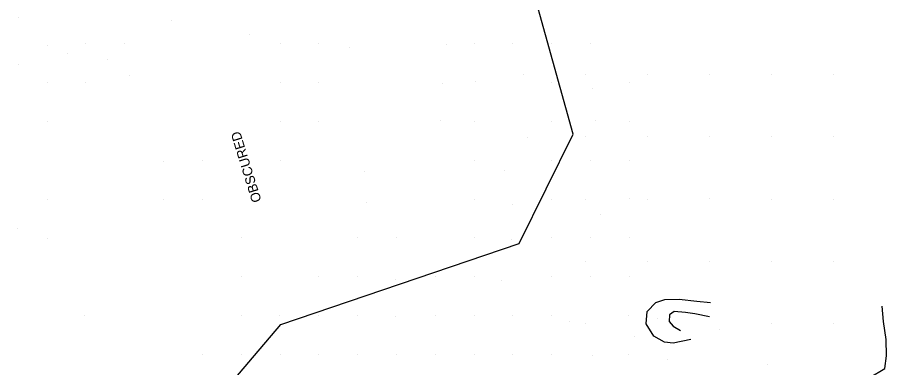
# Model space of a CAD drawing. Extents: x 524772 to 528246, y 273285 to 283088.
# Drawn here: x 527181.2 to 527317.8, y 274859.7 to 274914.7 of the extents above; entities that cross this region are included whole.
import ezdxf

# ---------------------------------------------------------------- set-up
doc = ezdxf.new("R2010")
doc.units = 0
for name, color, linetype in [('PH Exist DTM Breakline', 7, 'Continuous'), ('PH Exist DTM Obscure Area', 7, 'Continuous'), ('PH Exist DTM Obscure Area Text', 7, 'Continuous'), ('PH Exist DTM Point', 7, 'Continuous')]:
    doc.layers.add(name, color=color, linetype=linetype)

msp = doc.modelspace()

# ---------------------------------------------------------------- linework, layer by layer
at = {"layer": 'PH Exist DTM Breakline'}
for points in [[(527287, 274864.1), (527284.25, 274863.56), (527282.89, 274863.68), (527281.18, 274864.65), (527280.02, 274866.57), (527280.18, 274868.54), (527281.52, 274869.95), (527282.93, 274870.39), (527285.19, 274870.48), (527287.96, 274870.15), (527290.11, 274869.94)], [(527271.15, 274837.77), (527278.4, 274842.24), (527286.33, 274846.53), (527291.36, 274848.79), (527295.71, 274850.41), (527301.1, 274852.6), (527304.14, 274853.89), (527307.96, 274855.03), (527311.22, 274856.23), (527313.42, 274857.08), (527315.02, 274858.09), (527317.47, 274859.54), (527317.76, 274861.55), (527317.68, 274864.13), (527317.28, 274866.96), (527317.07, 274869.38)], [(527289.96, 274867.66), (527287.65, 274868.18), (527286.2, 274868.38), (527284.4, 274868.53), (527283.69, 274868), (527283.62, 274866.93), (527284.22, 274866.22), (527285.39, 274865.52)]]:
    msp.add_lwpolyline(points, dxfattribs=at)
at = {"layer": 'PH Exist DTM Obscure Area'}
msp.add_lwpolyline([(527193.38, 274832.02), (527222.62, 274866.47), (527260.08, 274879.19), (527268.55, 274896.41), (527257.79, 274935.01)], dxfattribs=at)
at = {"layer": 'PH Exist DTM Point'}
for p, q in [((527181.36, 274914.74), (527181.36, 274914.74)), ((527205.52, 274914.28), (527205.52, 274914.28)), ((527217.68, 274912.04), (527217.68, 274912.04)), ((527185.95, 274910.34), (527185.95, 274910.34)), ((527192.01, 274910.64), (527192.01, 274910.64)), ((527198.12, 274910.57), (527198.12, 274910.57)), ((527222.5, 274910.57), (527222.5, 274910.57)), ((527228.6, 274910.57), (527228.6, 274910.57)), ((527233.38, 274910.08), (527233.38, 274910.08)), ((527248.63, 274910.49), (527248.63, 274910.49)), ((527252.98, 274910.57), (527252.98, 274910.57)), ((527259.08, 274910.57), (527259.08, 274910.57)), ((527265.17, 274910.59), (527265.17, 274910.59)), ((527271.27, 274910.57), (527271.27, 274910.57)), ((527189.07, 274909.13), (527189.07, 274909.13)), ((527181.47, 274907.26), (527181.47, 274907.26)), ((527195.47, 274908.15), (527195.47, 274908.15)), ((527198.86, 274905.65), (527198.86, 274905.65)), ((527260.72, 274905.7), (527260.72, 274905.7)), ((527270.48, 274905.7), (527270.48, 274905.7)), ((527280.23, 274905.7), (527280.23, 274905.7)), ((527289.98, 274905.7), (527289.98, 274905.7)), ((527299.74, 274905.7), (527299.74, 274905.7)), ((527309.49, 274905.7), (527309.49, 274905.7)), ((527185.92, 274904.49), (527185.92, 274904.49)), ((527192.02, 274904.46), (527192.02, 274904.46)), ((527222.5, 274904.48), (527222.5, 274904.48)), ((527228.6, 274904.48), (527228.6, 274904.48)), ((527247.96, 274904.39), (527247.96, 274904.39)), ((527253.13, 274904.59), (527253.13, 274904.59)), ((527265.17, 274904.48), (527265.17, 274904.48)), ((527277.36, 274904.48), (527277.36, 274904.48)), ((527271.62, 274903.59), (527271.62, 274903.59)), ((527185.92, 274898.38), (527185.92, 274898.38)), ((527222.5, 274898.38), (527222.5, 274898.38)), ((527228.6, 274898.38), (527228.6, 274898.38)), ((527247.69, 274898.59), (527247.69, 274898.59)), ((527252.98, 274898.38), (527252.98, 274898.38)), ((527265.17, 274898.38), (527265.17, 274898.38)), ((527272.05, 274898.53), (527272.05, 274898.53)), ((527277.36, 274898.38), (527277.36, 274898.38)), ((527270.48, 274895.95), (527270.48, 274895.95)), ((527280.23, 274895.95), (527280.23, 274895.95)), ((527289.98, 274895.95), (527289.98, 274895.95)), ((527299.74, 274895.95), (527299.74, 274895.95)), ((527309.49, 274895.95), (527309.49, 274895.95)), ((527261.43, 274895.94), (527261.43, 274895.94)), ((527204.25, 274892.16), (527204.25, 274892.16)), ((527210.31, 274892.28), (527210.31, 274892.28)), ((527222.5, 274892.28), (527222.5, 274892.28)), ((527252.98, 274892.28), (527252.98, 274892.28)), ((527265.18, 274892.3), (527265.18, 274892.3)), ((527271.29, 274892.2), (527271.29, 274892.2)), ((527277.34, 274892.32), (527277.34, 274892.32)), ((527235.8, 274890.57), (527235.8, 274890.57)), ((527257.74, 274890.66), (527257.74, 274890.66)), ((527185.93, 274886.17), (527185.93, 274886.17)), ((527204.21, 274886.19), (527204.21, 274886.19)), ((527210.31, 274886.17), (527210.31, 274886.17)), ((527236.03, 274885.72), (527236.03, 274885.72)), ((527252.98, 274886.19), (527252.98, 274886.19)), ((527258.99, 274885.41), (527258.99, 274885.41)), ((527265.19, 274886.19), (527265.19, 274886.19)), ((527270.48, 274886.19), (527270.48, 274886.19)), ((527277.36, 274886.2), (527277.36, 274886.2)), ((527280.23, 274886.19), (527280.23, 274886.19)), ((527289.96, 274886.21), (527289.96, 274886.21)), ((527299.74, 274886.19), (527299.74, 274886.19)), ((527309.49, 274886.19), (527309.49, 274886.19)), ((527272.78, 274883.71), (527272.78, 274883.71)), ((527181.25, 274881.61), (527181.25, 274881.61)), ((527185.93, 274880.06), (527185.93, 274880.06)), ((527216.4, 274880.09), (527216.4, 274880.09)), ((527234.69, 274880.09), (527234.69, 274880.09)), ((527240.79, 274880.08), (527240.79, 274880.08)), ((527252.98, 274880.09), (527252.98, 274880.09)), ((527258.8, 274879.83), (527258.8, 274879.83)), ((527265.16, 274880.09), (527265.16, 274880.09)), ((527271.27, 274880.09), (527271.27, 274880.09)), ((527277.36, 274880.09), (527277.36, 274880.09)), ((527270.48, 274876.44), (527270.48, 274876.44)), ((527280.23, 274876.44), (527280.23, 274876.44)), ((527290.01, 274876.43), (527290.01, 274876.43)), ((527299.74, 274876.44), (527299.74, 274876.44)), ((527309.49, 274876.44), (527309.49, 274876.44)), ((527216.4, 274874), (527216.4, 274874)), ((527228.6, 274874), (527228.6, 274874)), ((527234.69, 274874), (527234.69, 274874)), ((527240.69, 274873.51), (527240.69, 274873.51)), ((527246.88, 274874), (527246.88, 274874)), ((527253.03, 274873.96), (527253.03, 274873.96)), ((527257.21, 274873.42), (527257.21, 274873.42)), ((527265.17, 274874), (527265.17, 274874)), ((527271.27, 274873.98), (527271.27, 274873.98)), ((527277.36, 274874), (527277.36, 274874)), ((527191.77, 274867.83), (527191.77, 274867.83)), ((527216.4, 274867.91), (527216.4, 274867.91)), ((527222.49, 274867.88), (527222.49, 274867.88)), ((527228.6, 274867.9), (527228.6, 274867.9)), ((527234.71, 274867.9), (527234.71, 274867.9)), ((527240.59, 274867.68), (527240.59, 274867.68)), ((527246.88, 274867.9), (527246.88, 274867.9)), ((527252.98, 274867.9), (527252.98, 274867.9)), ((527259.08, 274867.88), (527259.08, 274867.88)), ((527265.17, 274867.9), (527265.17, 274867.9)), ((527277.27, 274867.87), (527277.27, 274867.87)), ((527281.71, 274867.36), (527281.71, 274867.36)), ((527267.94, 274866.96), (527267.94, 274866.96)), ((527270.48, 274866.69), (527270.48, 274866.69)), ((527299.74, 274866.69), (527299.74, 274866.69)), ((527309.49, 274866.69), (527309.49, 274866.69)), ((527278.2, 274864.64), (527278.2, 274864.64)), ((527291.47, 274865.67), (527291.47, 274865.67)), ((527216.4, 274861.82), (527216.4, 274861.82)), ((527210.31, 274861.8), (527210.31, 274861.8)), ((527222.52, 274861.81), (527222.52, 274861.81)), ((527228.6, 274861.8), (527228.6, 274861.8)), ((527234.7, 274861.79), (527234.7, 274861.79)), ((527240.79, 274861.8), (527240.79, 274861.8)), ((527246.88, 274861.8), (527246.88, 274861.8)), ((527252.98, 274861.8), (527252.98, 274861.8)), ((527259.08, 274861.8), (527259.08, 274861.8)), ((527265.19, 274861.79), (527265.19, 274861.79)), ((527271.57, 274861.6), (527271.57, 274861.6)), ((527277.22, 274861.76), (527277.22, 274861.76)), ((527283.4, 274861.04), (527283.4, 274861.04)), ((527299, 274860.2), (527299, 274860.2))]:
    msp.add_line(p, q, dxfattribs=at)

# ---------------------------------------------------------------- texts
at = {"layer": 'PH Exist DTM Obscure Area Text'}
msp.add_text('OBSCURED', height=1.524, rotation=107.1924, dxfattribs=at).set_placement((527219.61, 274885.93))

doc.saveas('drawing.dxf')
